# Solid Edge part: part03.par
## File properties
Author: Administrator
Template: normal.par
Last saved by: TIET
Revision: 15
Application: Solid Edge
Accuracy: 0.99
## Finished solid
Body 1: solid body, 54 faces, 136 edges, 72 vertices.
  Faces by surface: cylinder 40, plane 14
  Edges by curve: circle 74, line 50, ellipse 12
Bounding box of the edges (mm): 320.500 x 112.000 x 70.000, from (-118.4884, -56, -35) to (202.0116, 56, 35).
Cylindrical faces by radius (mm): R5 x8, R6 x2, R12 x1, R13 x8, R17.5 x1, R26 x1, R31.5 x3, R35 x2, R72.03 x8, R78 x4, R207.0766 x1, R207.2725 x1
Planar faces by outward normal: +y 1, +z 4, -y 1, -z 4, oblique 4
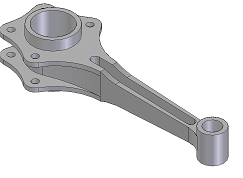
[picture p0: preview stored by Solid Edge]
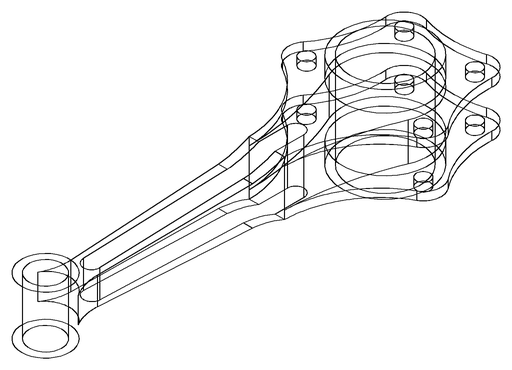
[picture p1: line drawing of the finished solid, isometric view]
